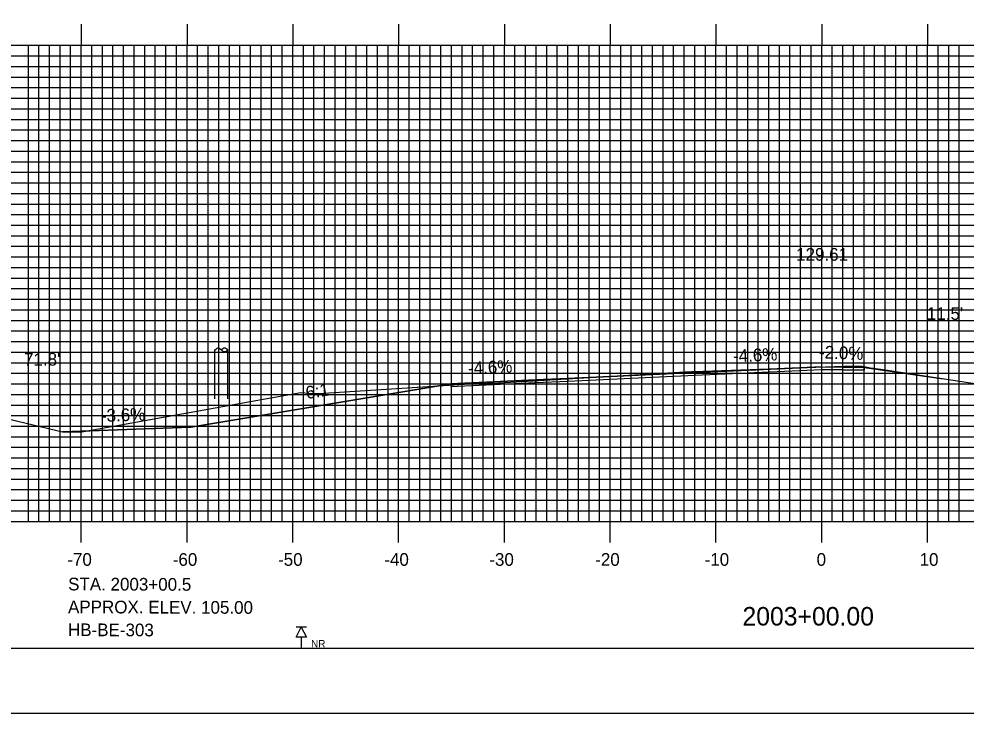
# Model space of a CAD drawing. Extents: x 851533 to 851876, y 366605 to 366825.
# Drawn here: x 851622.6 to 851712.1, y 366604.9 to 366670.5 of the extents above; entities that cross this region are included whole.
import ezdxf

# ---------------------------------------------------------------- set-up
doc = ezdxf.new("R2010")
doc.units = 0
for name, color, linetype in [('ANNOTATION', 7, 'Continuous'), ('BORDER', 7, 'Continuous'), ('BORING - NO REFUSAL', 7, 'Continuous'), ('D_Roadway_Centerline', 7, 'Continuous'), ('D_Roadway_Centerline_Text', 7, 'Continuous'), ('D_Roadway_Edge_Shoulder', 7, 'Continuous'), ('D_Roadway_Edge_TW', 7, 'Continuous'), ('D_Roadway_SlopeLines', 7, 'Continuous'), ('D_Text_Standard', 7, 'Continuous'), ('H_V ANNOTATION', 7, 'Continuous'), ('M_Roadway_Centerline', 7, 'Continuous'), ('MAJOR', 7, 'Continuous'), ('MINOR', 7, 'Continuous'), ('PLOT BOUNDARY', 7, 'Continuous'), ('S_Roadway_Centerline', 7, 'Continuous'), ('S_Utilities_Pole_StreetLight', 7, 'Continuous')]:
    doc.layers.add(name, color=color, linetype=linetype)

msp = doc.modelspace()

# ---------------------------------------------------------------- linework, layer by layer
at = {"layer": 'BORDER'}
msp.add_lwpolyline([(851548.852, 366611.055), (851868.852, 366611.055), (851868.852, 366821.055), (851548.852, 366821.055)], close=True, dxfattribs=at)
at = {"layer": 'BORING - NO REFUSAL'}
for p, q in [((851649.731, 366613.055), (851648.772, 366613.055)), ((851649.252, 366612.096), (851649.252, 366611.037))]:
    msp.add_line(p, q, dxfattribs=at)
msp.add_lwpolyline([(851649.252, 366613.055), (851649.731, 366612.096), (851648.772, 366612.096)], close=True, dxfattribs=at)
at = {"layer": 'D_Roadway_Centerline'}
for p, q in [((851698.451, 366637.666), (851702.451, 366637.586)), ((851698.451, 366637.416), (851702.451, 366637.336))]:
    msp.add_line(p, q, dxfattribs=at)
msp.add_lwpolyline([(851626.694, 366631.52), (851638.799, 366631.954), (851638.801, 366631.954), (851663.388, 366636.052), (851663.4, 366636.054), (851671.401, 366636.422), (851672.131, 366636.456), (851674.452, 366636.562), (851686.451, 366637.114), (851690.831, 366637.316), (851698.451, 366637.666), (851702.451, 366637.586), (851702.451, 366637.586)], dxfattribs=at)
at = {"layer": 'D_Roadway_Edge_Shoulder'}
for points in [[(851698.451, 366637.666), (851702.451, 366637.586), (851702.451, 366637.336), (851698.451, 366637.416)], [(851671.401, 366636.422), (851663.4, 366636.054), (851663.4, 366635.804), (851671.401, 366636.172)]]:
    msp.add_lwpolyline(points, close=True, dxfattribs=at)
at = {"layer": 'D_Roadway_Edge_TW'}
for points in [[(851686.451, 366637.114), (851674.452, 366636.562), (851674.452, 366636.312), (851686.451, 366636.864)], [(851698.451, 366637.666), (851686.451, 366637.114), (851686.451, 366636.864), (851698.451, 366637.416)], [(851674.452, 366636.562), (851671.401, 366636.422), (851671.401, 366636.172), (851674.452, 366636.312)]]:
    msp.add_lwpolyline(points, close=True, dxfattribs=at)
msp.add_lwpolyline([(851674.452, 366636.312), (851674.452, 366636.562)], dxfattribs=at)
at = {"layer": 'D_Roadway_SlopeLines'}
msp.add_line((851702.451, 366637.586), (851709.932, 366636.541), dxfattribs=at)
for points in [[(851663.4, 366636.054), (851638.801, 366631.954)], [(851638.801, 366631.954), (851626.694, 366631.52)]]:
    msp.add_lwpolyline(points, dxfattribs=at)
at = {"layer": 'MAJOR'}
for p, q in [((851628.452, 366670.059), (851628.452, 366668.055)), ((851638.452, 366670.059), (851638.452, 366668.055)), ((851648.452, 366670.059), (851648.452, 366668.055)), ((851658.452, 366670.059), (851658.452, 366668.055)), ((851668.452, 366670.059), (851668.452, 366668.055)), ((851678.452, 366670.059), (851678.452, 366668.055)), ((851688.452, 366670.059), (851688.452, 366668.055)), ((851698.452, 366670.059), (851698.452, 366668.055)), ((851708.452, 366670.059), (851708.452, 366668.055)), ((851558.452, 366668.055), (851838.452, 366668.055)), ((851558.452, 366668.055), (851838.452, 366668.055)), ((851628.452, 366623.055), (851628.452, 366668.055)), ((851638.452, 366623.055), (851638.452, 366668.055)), ((851648.452, 366623.055), (851648.452, 366668.055)), ((851658.452, 366623.055), (851658.452, 366668.055)), ((851668.452, 366623.055), (851668.452, 366668.055)), ((851678.452, 366623.055), (851678.452, 366668.055)), ((851688.452, 366623.055), (851688.452, 366668.055)), ((851698.452, 366623.055), (851698.452, 366668.055)), ((851708.452, 366623.055), (851708.452, 366668.055)), ((851558.452, 366663.055), (851838.452, 366663.055)), ((851558.452, 366658.055), (851838.452, 366658.055)), ((851558.452, 366653.055), (851838.452, 366653.055)), ((851558.452, 366648.055), (851838.452, 366648.055)), ((851558.452, 366643.055), (851838.452, 366643.055)), ((851558.452, 366638.055), (851838.452, 366638.055)), ((851558.452, 366633.055), (851838.452, 366633.055)), ((851558.452, 366628.055), (851838.452, 366628.055)), ((851558.452, 366623.055), (851838.452, 366623.055)), ((851558.452, 366623.055), (851838.452, 366623.055)), ((851628.452, 366621.051), (851628.452, 366623.055)), ((851638.452, 366621.051), (851638.452, 366623.055)), ((851648.452, 366621.051), (851648.452, 366623.055)), ((851658.452, 366621.051), (851658.452, 366623.055)), ((851668.452, 366621.051), (851668.452, 366623.055)), ((851678.452, 366621.051), (851678.452, 366623.055)), ((851688.452, 366621.051), (851688.452, 366623.055)), ((851698.452, 366621.051), (851698.452, 366623.055)), ((851708.452, 366621.051), (851708.452, 366623.055))]:
    msp.add_line(p, q, dxfattribs=at)
at = {"layer": 'MINOR'}
for p, q in [((851623.452, 366623.055), (851623.452, 366668.055)), ((851624.452, 366623.055), (851624.452, 366668.055)), ((851625.452, 366623.055), (851625.452, 366668.055)), ((851626.452, 366623.055), (851626.452, 366668.055)), ((851627.452, 366623.055), (851627.452, 366668.055)), ((851629.452, 366623.055), (851629.452, 366668.055)), ((851630.452, 366623.055), (851630.452, 366668.055)), ((851631.452, 366623.055), (851631.452, 366668.055)), ((851632.452, 366623.055), (851632.452, 366668.055)), ((851633.452, 366623.055), (851633.452, 366668.055)), ((851634.452, 366623.055), (851634.452, 366668.055)), ((851635.452, 366623.055), (851635.452, 366668.055)), ((851636.452, 366623.055), (851636.452, 366668.055)), ((851637.452, 366623.055), (851637.452, 366668.055)), ((851639.452, 366623.055), (851639.452, 366668.055)), ((851640.452, 366623.055), (851640.452, 366668.055)), ((851641.452, 366623.055), (851641.452, 366668.055)), ((851642.452, 366623.055), (851642.452, 366668.055)), ((851643.452, 366623.055), (851643.452, 366668.055)), ((851644.452, 366623.055), (851644.452, 366668.055)), ((851645.452, 366623.055), (851645.452, 366668.055)), ((851646.452, 366623.055), (851646.452, 366668.055)), ((851647.452, 366623.055), (851647.452, 366668.055)), ((851649.452, 366623.055), (851649.452, 366668.055)), ((851650.452, 366623.055), (851650.452, 366668.055)), ((851651.452, 366623.055), (851651.452, 366668.055)), ((851652.452, 366623.055), (851652.452, 366668.055)), ((851653.452, 366623.055), (851653.452, 366668.055)), ((851654.452, 366623.055), (851654.452, 366668.055)), ((851655.452, 366623.055), (851655.452, 366668.055)), ((851656.452, 366623.055), (851656.452, 366668.055)), ((851657.452, 366623.055), (851657.452, 366668.055)), ((851659.452, 366623.055), (851659.452, 366668.055)), ((851660.452, 366623.055), (851660.452, 366668.055)), ((851661.452, 366623.055), (851661.452, 366668.055)), ((851662.452, 366623.055), (851662.452, 366668.055)), ((851663.452, 366623.055), (851663.452, 366668.055)), ((851664.452, 366623.055), (851664.452, 366668.055)), ((851665.452, 366623.055), (851665.452, 366668.055)), ((851666.452, 366623.055), (851666.452, 366668.055)), ((851667.452, 366623.055), (851667.452, 366668.055)), ((851669.452, 366623.055), (851669.452, 366668.055)), ((851670.452, 366623.055), (851670.452, 366668.055)), ((851671.452, 366623.055), (851671.452, 366668.055)), ((851672.452, 366623.055), (851672.452, 366668.055)), ((851673.452, 366623.055), (851673.452, 366668.055)), ((851674.452, 366623.055), (851674.452, 366668.055)), ((851675.452, 366623.055), (851675.452, 366668.055)), ((851676.452, 366623.055), (851676.452, 366668.055)), ((851677.452, 366623.055), (851677.452, 366668.055)), ((851679.452, 366623.055), (851679.452, 366668.055)), ((851680.452, 366623.055), (851680.452, 366668.055)), ((851681.452, 366623.055), (851681.452, 366668.055)), ((851682.452, 366623.055), (851682.452, 366668.055)), ((851683.452, 366623.055), (851683.452, 366668.055)), ((851684.452, 366623.055), (851684.452, 366668.055)), ((851685.452, 366623.055), (851685.452, 366668.055)), ((851686.452, 366623.055), (851686.452, 366668.055)), ((851687.452, 366623.055), (851687.452, 366668.055)), ((851689.452, 366623.055), (851689.452, 366668.055)), ((851690.452, 366623.055), (851690.452, 366668.055)), ((851691.452, 366623.055), (851691.452, 366668.055)), ((851692.452, 366623.055), (851692.452, 366668.055)), ((851693.452, 366623.055), (851693.452, 366668.055)), ((851694.452, 366623.055), (851694.452, 366668.055)), ((851695.452, 366623.055), (851695.452, 366668.055)), ((851696.452, 366623.055), (851696.452, 366668.055)), ((851697.452, 366623.055), (851697.452, 366668.055)), ((851699.452, 366623.055), (851699.452, 366668.055)), ((851700.452, 366623.055), (851700.452, 366668.055)), ((851701.452, 366623.055), (851701.452, 366668.055)), ((851702.452, 366623.055), (851702.452, 366668.055)), ((851703.452, 366623.055), (851703.452, 366668.055)), ((851704.452, 366623.055), (851704.452, 366668.055)), ((851705.452, 366623.055), (851705.452, 366668.055)), ((851706.452, 366623.055), (851706.452, 366668.055)), ((851707.452, 366623.055), (851707.452, 366668.055)), ((851709.452, 366623.055), (851709.452, 366668.055)), ((851710.452, 366623.055), (851710.452, 366668.055)), ((851711.452, 366623.055), (851711.452, 366668.055)), ((851558.452, 366667.055), (851838.452, 366667.055)), ((851558.452, 366666.055), (851838.452, 366666.055)), ((851558.452, 366665.055), (851838.452, 366665.055)), ((851558.452, 366664.055), (851838.452, 366664.055)), ((851558.452, 366662.055), (851838.452, 366662.055)), ((851558.452, 366661.055), (851838.452, 366661.055)), ((851558.452, 366660.055), (851838.452, 366660.055)), ((851558.452, 366659.055), (851838.452, 366659.055)), ((851558.452, 366657.055), (851838.452, 366657.055)), ((851558.452, 366656.055), (851838.452, 366656.055)), ((851558.452, 366655.055), (851838.452, 366655.055)), ((851558.452, 366654.055), (851838.452, 366654.055)), ((851558.452, 366652.055), (851838.452, 366652.055)), ((851558.452, 366651.055), (851838.452, 366651.055)), ((851558.452, 366650.055), (851838.452, 366650.055)), ((851558.452, 366649.055), (851838.452, 366649.055)), ((851558.452, 366647.055), (851838.452, 366647.055)), ((851558.452, 366646.055), (851838.452, 366646.055)), ((851558.452, 366645.055), (851838.452, 366645.055)), ((851558.452, 366644.055), (851838.452, 366644.055)), ((851558.452, 366642.055), (851838.452, 366642.055)), ((851558.452, 366641.055), (851838.452, 366641.055)), ((851558.452, 366640.055), (851838.452, 366640.055)), ((851558.452, 366639.055), (851838.452, 366639.055)), ((851558.452, 366637.055), (851838.452, 366637.055)), ((851558.452, 366636.055), (851838.452, 366636.055)), ((851558.452, 366635.055), (851838.452, 366635.055)), ((851558.452, 366634.055), (851838.452, 366634.055)), ((851558.452, 366632.055), (851838.452, 366632.055)), ((851558.452, 366631.055), (851838.452, 366631.055)), ((851558.452, 366630.055), (851838.452, 366630.055)), ((851558.452, 366629.055), (851838.452, 366629.055)), ((851558.452, 366627.055), (851838.452, 366627.055)), ((851558.452, 366626.055), (851838.452, 366626.055)), ((851558.452, 366625.055), (851838.452, 366625.055)), ((851558.452, 366624.055), (851838.452, 366624.055))]:
    msp.add_line(p, q, dxfattribs=at)
at = {"layer": 'PLOT BOUNDARY'}
msp.add_lwpolyline([(851532.665, 366604.937), (851872.665, 366604.937), (851872.665, 366824.937), (851532.665, 366824.937)], close=True, dxfattribs=at)
at = {"layer": 'S_Roadway_Centerline'}
msp.add_lwpolyline([(851617.557, 366633.691), (851626.695, 366631.521), (851628.494, 366631.52), (851645.833, 366634.624), (851649.216, 366635.231), (851650.334, 366635.153), (851650.486, 366635.141), (851650.872, 366635.155), (851665.665, 366636.08), (851667.952, 366636.136), (851685.53, 366637.176), (851686.126, 366637.212), (851686.303, 366637.224), (851686.443, 366637.219), (851687.234, 366637.252), (851700.584, 366637.715), (851702.268, 366637.726), (851703.077, 366637.576), (851704.039, 366637.43), (851715.826, 366635.653)], dxfattribs=at)
at = {"layer": 'S_Utilities_Pole_StreetLight'}
for p, q in [((851641.071, 366634.649), (851641.068, 366639.268)), ((851641.071, 366639.268), (851641.227, 366639.379)), ((851641.539, 366639.379), (851641.696, 366639.268)), ((851641.852, 366639.379), (851641.696, 366639.268)), ((851641.696, 366639.268), (851641.852, 366639.157)), ((851642.321, 366639.268), (851642.165, 366639.379)), ((851642.165, 366639.157), (851642.321, 366639.268)), ((851642.321, 366634.649), (851642.318, 366639.268))]:
    msp.add_line(p, q, dxfattribs=at)
for centre, start, end in [((851641.383, 366639.158), 90, 125.26439), ((851641.383, 366639.158), 54.73561, 90), ((851642.008, 366639.158), 90, 125.26439), ((851642.008, 366639.379), 234.73561, 270), ((851642.008, 366639.158), 54.73561, 90), ((851642.008, 366639.379), 270, 305.26439)]:
    msp.add_arc(centre, 0.271, start, end, dxfattribs=at)

# ---------------------------------------------------------------- texts
at = {"layer": 'ANNOTATION'}
for s, rotation, p in [('-2.0%', 357.70964, (851698.178, 366638.479)), ('-4.6%', 2.6338, (851690.093, 366638.084)), ('-4.6%', 2.63363, (851665.042, 366636.932)), ('6:1', 9.46252, (851649.77, 366634.61)), ('-3.6%', 2.05312, (851630.333, 366632.452))]:
    msp.add_text(s, height=1.2, rotation=rotation, dxfattribs=at).set_placement(p)
at = {"layer": 'BORING - NO REFUSAL'}
for s, p in [('STA. 2003+00.5', (851627.21, 366616.533)), ('APPROX. ELEV. 105.00', (851627.203, 366614.373)), ('HB-BE-303', (851627.196, 366612.213))]:
    msp.add_text(s, height=1.2, rotation=359.81416, dxfattribs=at).set_placement(p)
msp.add_text('NR', height=0.6998, dxfattribs=at).set_placement((851650.184, 366611.14))
at = {"layer": 'D_Roadway_Centerline_Text'}
msp.add_text('129.61', height=1.2, dxfattribs=at).set_placement((851696.033, 366647.696))
at = {"layer": 'D_Text_Standard'}
for s, p in [("11.5'", (851708.39, 366642.103)), ("71.8'", (851623.048, 366637.776))]:
    msp.add_text(s, height=1.2, dxfattribs=at).set_placement(p)
at = {"layer": 'H_V ANNOTATION'}
for s, height, p in [('-70', 1.2, (851627.135, 366618.855)), ('-60', 1.2, (851637.103, 366618.855)), ('-50', 1.2, (851647.06, 366618.855)), ('-40', 1.2, (851657.103, 366618.855)), ('-30', 1.2, (851667.028, 366618.855)), ('-20', 1.2, (851677.039, 366618.855)), ('-10', 1.2, (851687.381, 366618.855)), ('0', 1.2, (851697.97, 366618.855)), ('10', 1.2, (851707.702, 366618.855)), ('2003+00.00', 1.75, (851690.96, 366613.211))]:
    msp.add_text(s, height=height, dxfattribs=at).set_placement(p)
at = {"layer": 'M_Roadway_Centerline'}
for s, p in [('C', (851686.297, 366637.224)), ('L', (851686.303, 366637.216))]:
    msp.add_text(s, height=0.0146, dxfattribs=at).set_placement(p)

doc.saveas('drawing.dxf')
